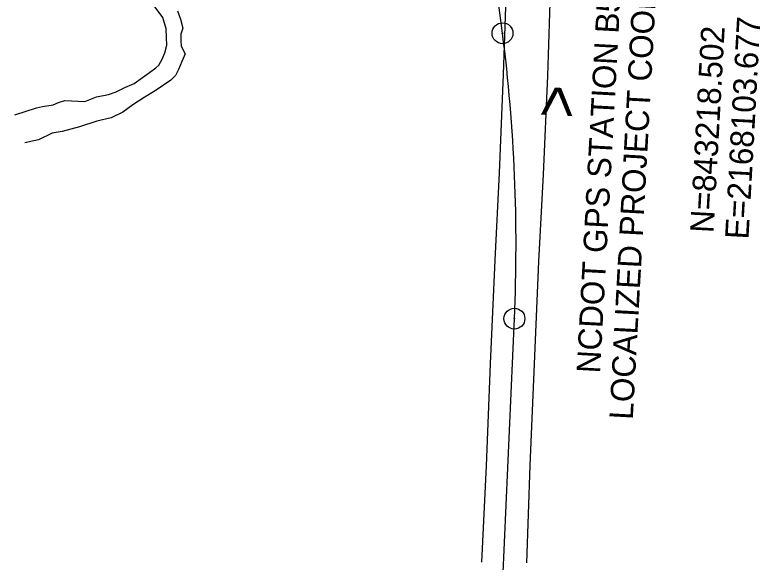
# Model space of a CAD drawing. Extents: x 2167298 to 2168977, y 841960 to 844561.
# Drawn here: x 2167834 to 2168204.9, y 842986.9 to 843259.3 of the extents above; entities that cross this region are included whole.
import ezdxf

# ---------------------------------------------------------------- set-up
doc = ezdxf.new("R2010")
doc.units = 0
for name, color, linetype in [('CTL GPS Vertical Text', 7, 'Continuous'), ('CTL Sheet Notes CELL', 7, 'Continuous'), ('Exist Hydro Stream or Body of Water', 7, 'Continuous'), ('Exist Roads EOP', 7, 'Continuous'), ('Prop Horizontal Alignment', 7, 'Continuous')]:
    doc.layers.add(name, color=color, linetype=linetype)

msp = doc.modelspace()

# ---------------------------------------------------------------- linework, layer by layer
at = {"layer": 'Exist Hydro Stream or Body of Water'}
for points in [[(2167907.73, 843258.06), (2167904.42, 843262.46), (2167901.24, 843266.42), (2167899.43, 843269.93), (2167897.04, 843273.21), (2167895.59, 843278.19), (2167894.81, 843281.76), (2167896.35, 843289.36), (2167897.69, 843294.83), (2167899.67, 843299.2), (2167901.74, 843302.08), (2167905.14, 843302.96), (2167908.64, 843305.5), (2167914.14, 843309.37)], [(2167915.01, 843261.26), (2167916.45, 843257.13), (2167917.63, 843252.79), (2167916.61, 843249.72), (2167916.58, 843246.42), (2167916.83, 843243.68), (2167918.83, 843239.9), (2167917.17, 843236.14), (2167915.45, 843232.08), (2167913.97, 843229.18), (2167911.58, 843226.81)], [(2167905.68, 843234.25), (2167907.37, 843237.21), (2167908.66, 843240.5), (2167909.59, 843244.2), (2167909.44, 843248.02), (2167909.27, 843252.62), (2167908.39, 843255.77), (2167907.73, 843258.06)], [(2167834.03, 843209.49), (2167844.75, 843213.07), (2167847.78, 843213.78), (2167853.1, 843214.61), (2167855.8, 843215.69), (2167858.9, 843216.77), (2167868.91, 843216.13), (2167874.68, 843218.6), (2167880.57, 843219.65), (2167884.39, 843221.08), (2167888.77, 843223.17), (2167893.43, 843225.21), (2167897.49, 843228.08), (2167901.1, 843230.6), (2167904.13, 843233.01), (2167905.68, 843234.25)], [(2167911.58, 843226.81), (2167903.83, 843221.46), (2167898.31, 843218.24), (2167892.72, 843214.47), (2167887.71, 843210.95), (2167881.87, 843208.05), (2167874.76, 843206.39), (2167866.18, 843203.59), (2167857.5, 843201.2), (2167852.58, 843200.48), (2167845.77, 843197.05), (2167839.05, 843195.7)]]:
    msp.add_lwpolyline(points, dxfattribs=at)
at = {"layer": 'Exist Roads EOP'}
for points in [[(2168088.8, 842986.5), (2168090.54, 843034.94), (2168092.62, 843085.63), (2168094.79, 843136.47), (2168097.17, 843179.92), (2168099.2, 843228.96), (2168100.75, 843276.01), (2168101.9, 843328.13), (2168102.88, 843383.52), (2168105.26, 843433.67), (2168108.45, 843504.42), (2168112.55, 843553.1), (2168114.28, 843603.6), (2168114.19, 843648.77), (2168111.04, 843696.23), (2168101.28, 843747.73)], [(2168088.8, 842986.5), (2168090.54, 843034.94), (2168092.62, 843085.63), (2168094.79, 843136.47), (2168097.17, 843179.92), (2168099.2, 843228.96), (2168100.75, 843276.01), (2168101.9, 843328.13), (2168102.88, 843383.52), (2168105.26, 843433.67), (2168108.45, 843504.42), (2168112.55, 843553.1), (2168114.28, 843603.6), (2168114.19, 843648.77), (2168111.04, 843696.23), (2168101.28, 843747.73)], [(2168066.47, 842986.79), (2168068.78, 843034.77), (2168070.69, 843085.52), (2168073.1, 843137.29), (2168075.19, 843180.69), (2168077.23, 843229.63), (2168078.87, 843277.87), (2168081.38, 843328.25), (2168085.18, 843384.71), (2168087.31, 843434.46), (2168090.6, 843505.16), (2168090.32, 843554.22), (2168091.17, 843603.38), (2168091.32, 843648.61), (2168088.6, 843694.65), (2168078.62, 843740.74)], [(2168066.47, 842986.79), (2168068.78, 843034.77), (2168070.69, 843085.52), (2168073.1, 843137.29), (2168075.19, 843180.69), (2168077.23, 843229.63), (2168078.87, 843277.87), (2168081.38, 843328.25), (2168085.18, 843384.71), (2168087.31, 843434.46), (2168090.6, 843505.16), (2168090.32, 843554.22), (2168091.17, 843603.38), (2168091.32, 843648.61), (2168088.6, 843694.65), (2168078.62, 843740.74)]]:
    msp.add_lwpolyline(points, dxfattribs=at)
at = {"layer": 'Prop Horizontal Alignment'}
for p, q in [((2168076.73, 843250.17), (2168030.57, 843611.57)), ((2168061.96, 842637.05), (2168082.64, 843108.09))]:
    msp.add_line(p, q, dxfattribs=at)
for centre, radius in [((2168076.73, 843250.17), 5.19), ((2168076.73, 843250.17), 0.167), ((2168082.64, 843108.09), 5.19), ((2168082.64, 843108.09), 0.167)]:
    msp.add_circle(centre, radius, dxfattribs=at)
msp.add_arc((2167250.45, 843144.63), 833, 357.48556, 7.27898, dxfattribs=at)

# ---------------------------------------------------------------- texts
at = {"layer": 'CTL GPS Vertical Text'}
for s, p in [('LOCALIZED PROJECT COORDINATES', (2168141.54, 843057.59)), ('NCDOT GPS STATION B5325-1', (2168125.23, 843080.7)), ('E=2168103.677', (2168199.13, 843147.39)), ('N=843218.502', (2168181.74, 843150.55))]:
    msp.add_text(s, height=11.6923, rotation=86.8779, dxfattribs=at).set_placement(p)
at = {"layer": 'CTL Sheet Notes CELL'}
msp.add_text('>', height=21.23, rotation=87.1906, dxfattribs=at).set_placement((2168113.73, 843207.38))

doc.saveas('drawing.dxf')
